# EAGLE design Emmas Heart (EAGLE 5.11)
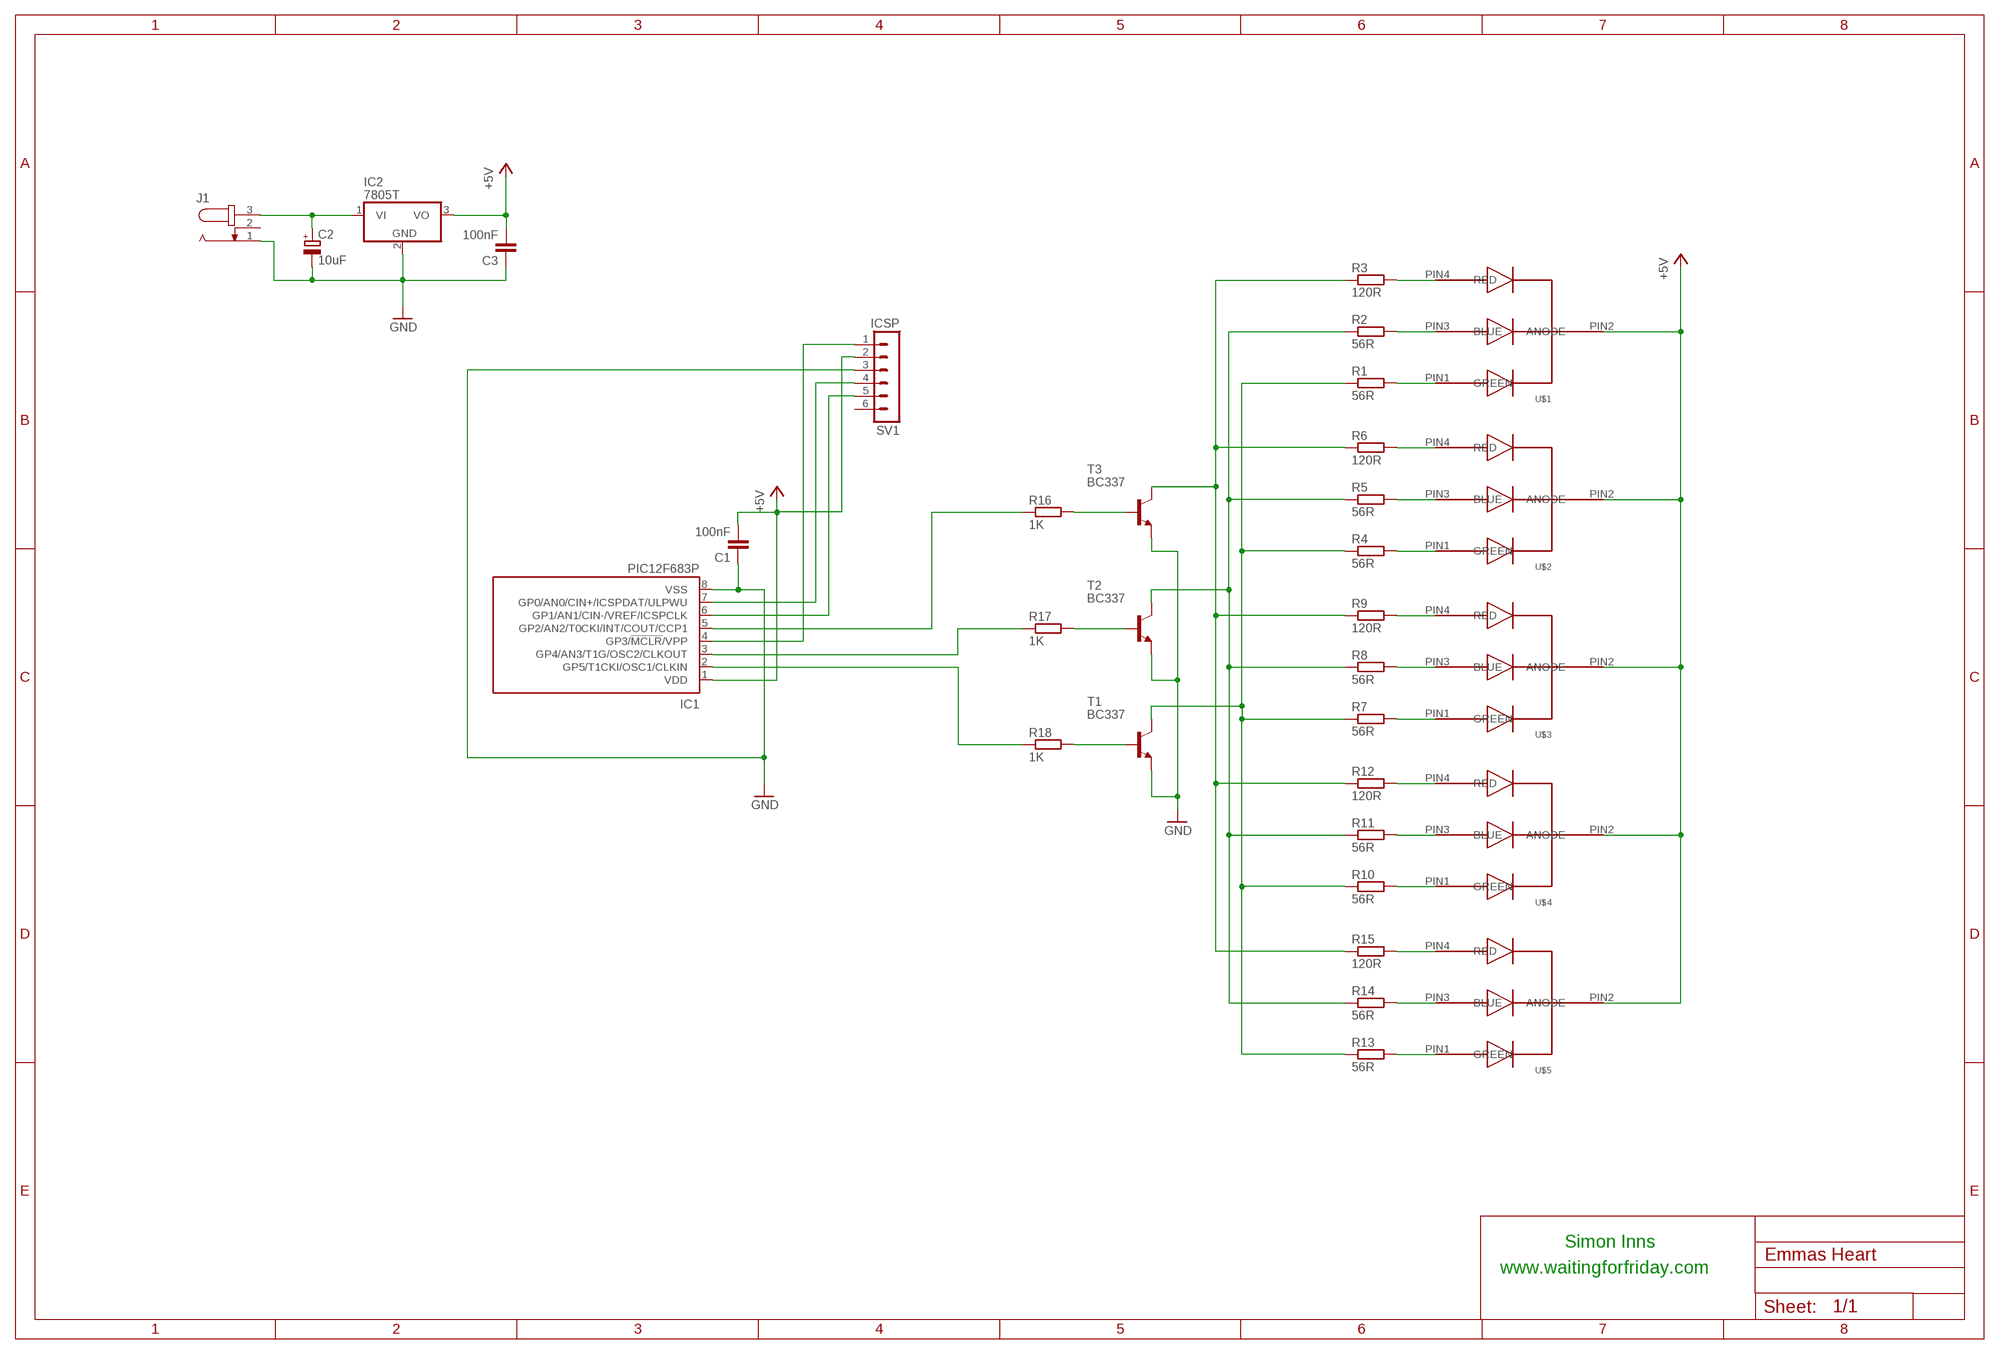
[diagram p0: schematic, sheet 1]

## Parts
C1  100nF  C-EU075-032X103  [C075-032X103]
C2  10uF  CPOL-EUE2.5-5  [E2,5-5]
C3  100nF  C-EU075-032X103  [C075-032X103]
IC1  PIC12F683P  [DIL8]
IC2  7805T  [TO220H]
J1  JACK-PLUG0  [SPC4077]
R1  56R  R-EU_0207/10  [0207/10]
R2  56R  R-EU_0207/10  [0207/10]
R3  120R  R-EU_0207/10  [0207/10]
R4  56R  R-EU_0207/10  [0207/10]
R5  56R  R-EU_0207/10  [0207/10]
R6  120R  R-EU_0207/10  [0207/10]
R7  56R  R-EU_0207/10  [0207/10]
R8  56R  R-EU_0207/10  [0207/10]
R9  120R  R-EU_0207/10  [0207/10]
R10  56R  R-EU_0207/10  [0207/10]
R11  56R  R-EU_0207/10  [0207/10]
R12  120R  R-EU_0207/10  [0207/10]
R13  56R  R-EU_0207/10  [0207/10]
R14  56R  R-EU_0207/10  [0207/10]
R15  120R  R-EU_0207/10  [0207/10]
R16  1K  R-EU_0207/10  [0207/10]
R17  1K  R-EU_0207/10  [0207/10]
R18  1K  R-EU_0207/10  [0207/10]
SV1  ICSP  MA06-1  [MA06-1]
T1  BC337  BC337-16-NPN-TO92-CBE  [TO92-CBE]
T2  BC337  BC337-16-NPN-TO92-CBE  [TO92-CBE]
T3  BC337  BC337-16-NPN-TO92-CBE  [TO92-CBE]
U$1  COMMON_ANODE_RGB_LED_KJ  [LED5MMRGB]
U$2  COMMON_ANODE_RGB_LED_KJ  [LED5MMRGB]
U$3  COMMON_ANODE_RGB_LED_KJ  [LED5MMRGB]
U$4  COMMON_ANODE_RGB_LED_KJ  [LED5MMRGB]
U$5  COMMON_ANODE_RGB_LED_KJ  [LED5MMRGB]

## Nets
+5V: C1.2 C3.2 IC1.1(VDD) IC2.3(VO) SV1.2 U$1.PIN2(ANODE) U$2.PIN2(ANODE) U$3.PIN2(ANODE) U$4.PIN2(ANODE) U$5.PIN2(ANODE)
GND: C1.1 C2.- C3.1 IC1.8(VSS) IC2.2(GND) J1.1 SV1.3 T1.E T2.E T3.E
N$1: C2.+ IC2.1(VI) J1.3
N$2: R3.1 R6.1 R9.1 R12.1 R15.1 T3.C
N$3: R2.1 R5.1 R8.1 R11.1 R14.1 T2.C
N$4: R1.1 R4.1 R7.1 R10.1 R13.1 T1.C
N$5: R3.2 U$1.PIN4(RED)
N$6: R2.2 U$1.PIN3(BLUE)
N$7: R1.2 U$1.PIN1(GREEN)
N$8: R6.2 U$2.PIN4(RED)
N$9: R5.2 U$2.PIN3(BLUE)
N$10: R4.2 U$2.PIN1(GREEN)
N$11: R9.2 U$3.PIN4(RED)
N$12: R8.2 U$3.PIN3(BLUE)
N$13: R7.2 U$3.PIN1(GREEN)
N$14: R12.2 U$4.PIN4(RED)
N$15: R11.2 U$4.PIN3(BLUE)
N$16: R10.2 U$4.PIN1(GREEN)
N$17: R15.2 U$5.PIN4(RED)
N$18: R14.2 U$5.PIN3(BLUE)
N$19: R13.2 U$5.PIN1(GREEN)
N$21: R16.2 T3.B
N$22: R17.2 T2.B
N$23: R18.2 T1.B
N$26: IC1.4(GP3/!MCLR!/VPP) SV1.1
N$27: IC1.7(GP0/AN0/CIN+/ICSPDAT/ULPWU) SV1.4
N$28: IC1.6(GP1/AN1/CIN-/VREF/ICSPCLK) SV1.5
N$29: IC1.5(GP2/AN2/T0CKI/INT/COUT/CCP1) R16.1
N$30: IC1.3(GP4/AN3/T1G/OSC2/CLKOUT) R17.1
N$31: IC1.2(GP5/T1CKI/OSC1/CLKIN) R18.1
Unconnected: J1.2 SV1.6

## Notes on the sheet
- Simon Inns
- www.waitingforfriday.com

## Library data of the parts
C1 C3 = rcl:C-EU: CAPACITOR, European symbol
C2 = rcl:CPOL-EU: POLARIZED CAPACITOR, European symbol
IC1 = microchip:PIC12F683: 8-Pin Flash-Based, 8-Bit CMOS Microcontrollers with nanoWatt Technology Source: http://ww1.microchip.com/downloads/en/DeviceDoc/41211D_.pdf; MF: MICROCHIP; MPN: PIC12F683-I/P; OC_FARNELL: 9759034; OC_NEWARK: 89H0442
IC2 = linear:78*: Positive VOLTAGE REGULATOR Source: http://cache.national.com/ds/LM/LM78L05.pdf http://www.fairchildsemi.com/ds/LM/LM7805.pdf
J1 = con-jack:JACK-PLUG: DC POWER JACK Power Jack, DC, Right Angle, Through Hole, Rated 5A at 16VDC, PC Terminals Distributor: Farnell (www.Farnell.de) Drawing: 84N1161.pdf / 84N1162.pdf Manufacturer: SPC Technology (www.spctechnology.com) Type: SPC4077 / SPC 4078; OC_FARNELL: unknown; OC_NEWARK: unknown
R1-R18 = rcl:R-EU_: RESISTOR, European symbol
SV1 = con-lstb:MA06-1: PIN HEADER; OC_FARNELL: unknown; OC_NEWARK: unknown
T1-T3 = transistor:*-NPN-: NPN Transistror BF959 corrected 2008.03.06
U$1-U$5 = simonslbr:COMMON_ANODE_RGB_LED_KJ: Common Anode RGB LED (5mm)

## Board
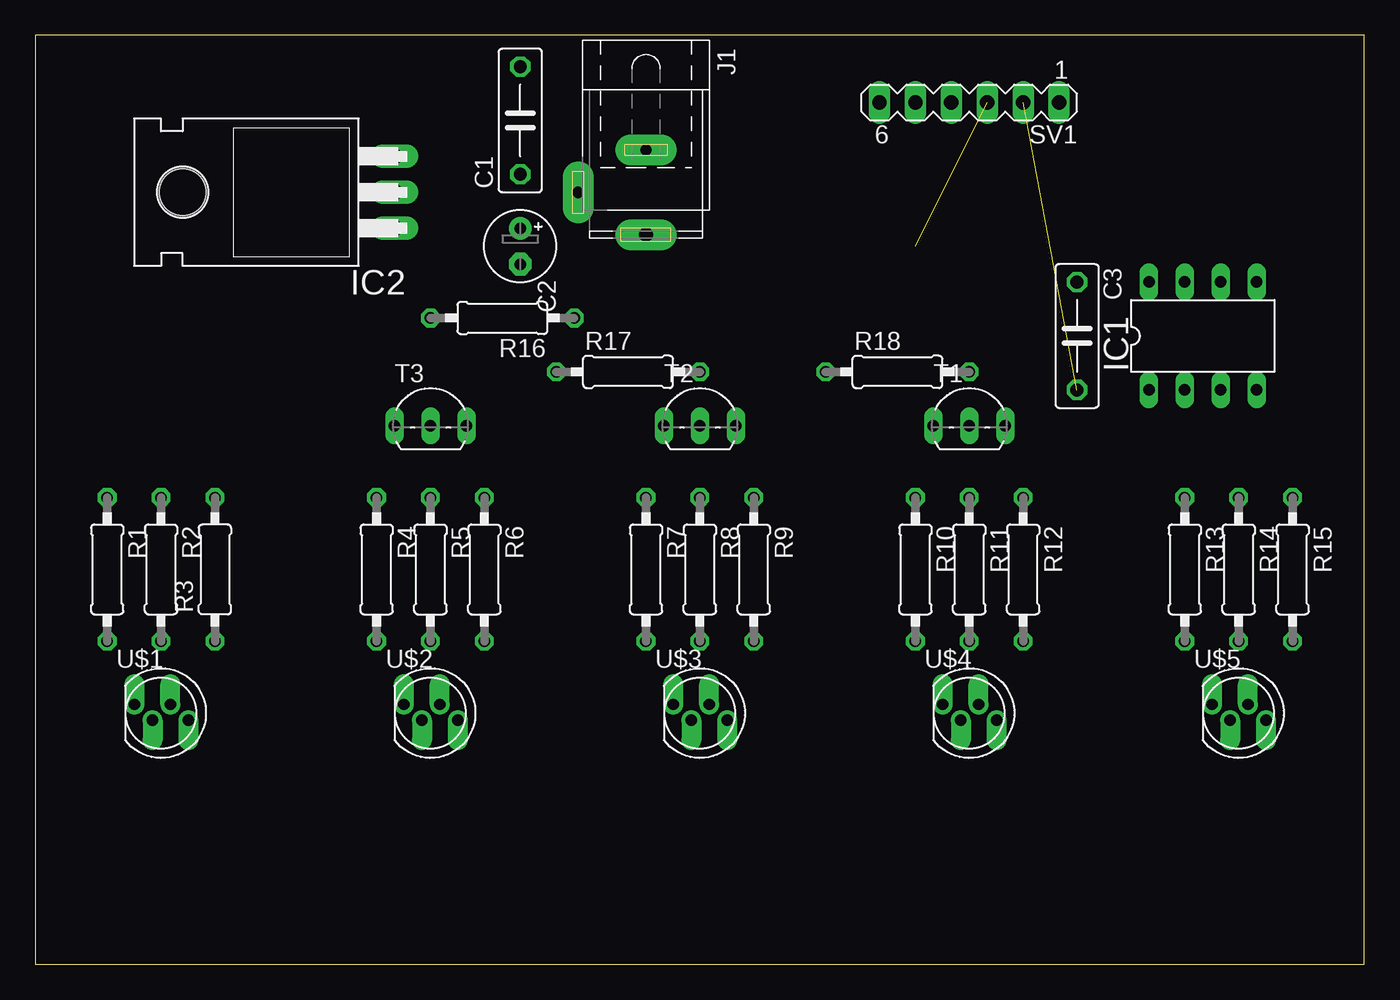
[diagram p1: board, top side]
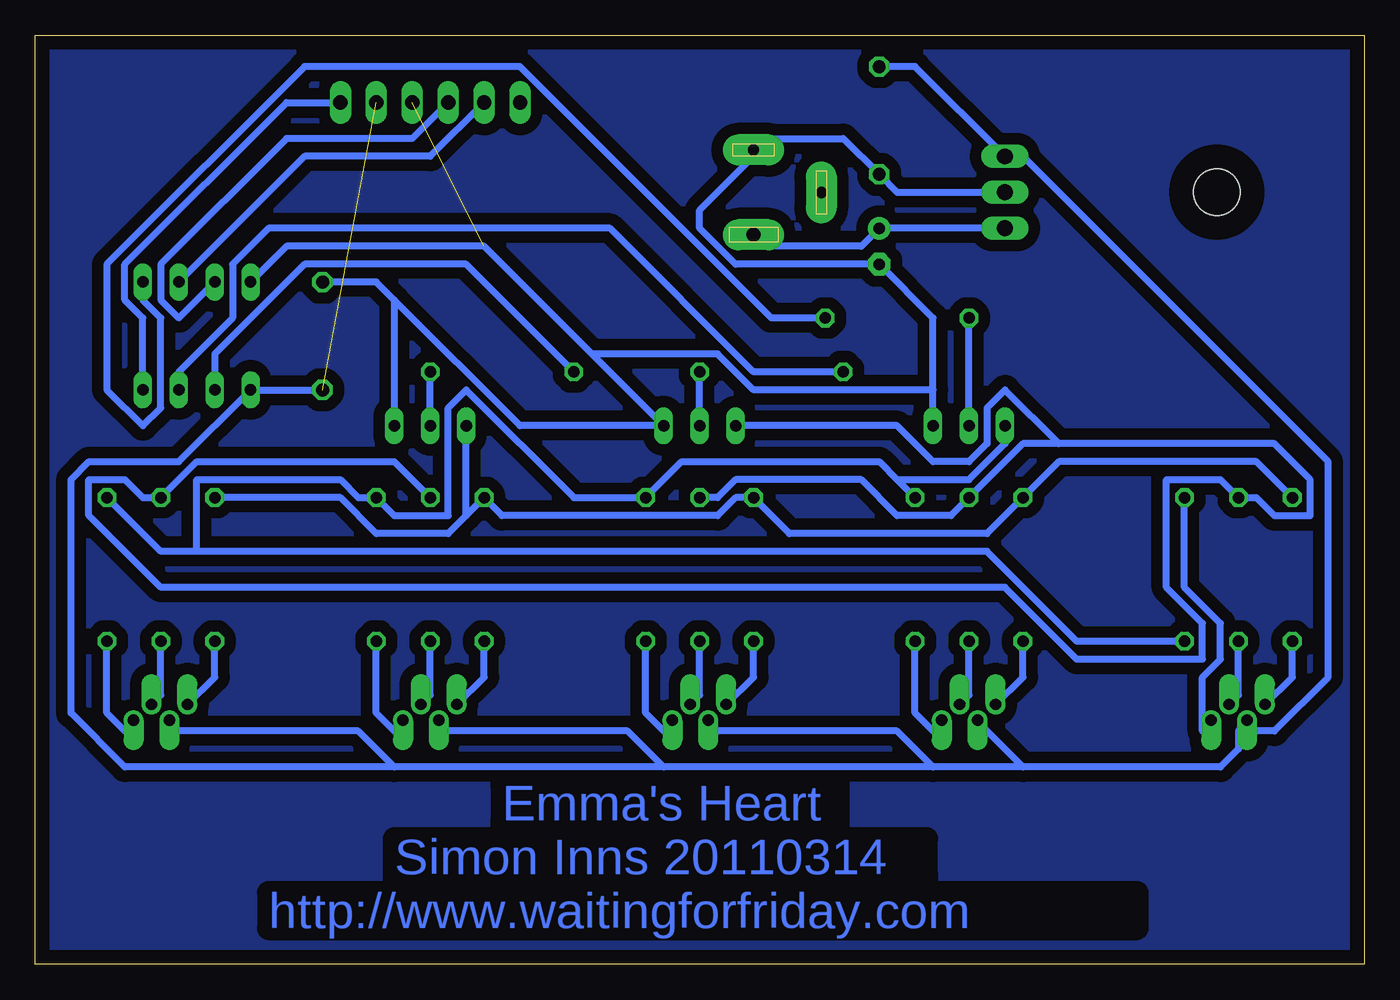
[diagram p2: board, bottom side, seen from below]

Size 93.96 x 65.71 mm. Coordinates in mm from the lower left corner, seen from the top.
Outline: 0,0 93.96,0 93.96,65.71 0,65.71 0,0
Copper layers (1*16): Top 0.035mm / dielectric 1.5mm / Bottom 0.035mm
Design rules "default *": minimum track width 20mil, minimum drill 24mil, track to track 8mil, track to pad 8mil, pad to pad 8mil, via to via 8mil, smd to smd 8mil, copper to edge 40mil, drill to drill 8mil, minimum pad ring 10mil, minimum via ring 8mil, stop-mask expansion 4mil, vias tented up to drill 0mil, thermal gap 10mil

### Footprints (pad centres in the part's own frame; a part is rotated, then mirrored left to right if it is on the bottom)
C075-032X103 = drill 0.914 octagon: 1 -3.81,0; 2 3.81,0
E2,5-5 = drill 0.813 pad 1.6 round: + -1.27,0 | drill 0.813 pad 1.6 octagon: - 1.27,0
DIL8 = drill 0.813 long: 1 -3.81,-3.81; 2 -1.27,-3.81; 3 1.27,-3.81; 4 3.81,-3.81; 5 3.81,3.81; 6 1.27,3.81; 7 -1.27,3.81; 8 -3.81,3.81
TO220H = drill 1.118 long: 1 -2.54,-10.16; 2 0,-10.16; 3 2.54,-10.16 | hole 3.302: 0,4.826
SPC4077 = drill 0.8 pad 2.184 long: 1 -3,0; 2 0,-4.8 | drill 1 pad 2.184 long: 3 3,0
0207/10 = drill 0.813 octagon: 1 -5.08,0; 2 5.08,0
MA06-1 = drill 1.016 long: 1 -6.35,0; 2 -3.81,0; 3 -1.27,0; 4 1.27,0; 5 3.81,0; 6 6.35,0
TO92-CBE = drill 0.813 long: B 0,0; C -2.54,0; E 2.54,0
LED5MMRGB = drill 0.8 pad 1.422 offset: PIN1 -1.88,0.61; PIN2 -0.61,-0.508; PIN3 0.66,0.61; PIN4 1.93,-0.508

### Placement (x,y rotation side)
C1  34.29,59.69 90 top
C2  34.29,50.8 270 top
C3  73.66,44.45 270 top
IC1  82.55,44.45 0 top
IC2  15.24,54.61 90 top
J1  43.18,54.61 270 top
R1  5.08,27.94 270 top
R2  8.89,27.94 270 top
R3  12.7,27.94 90 top
R4  24.13,27.94 270 top
R5  27.94,27.94 270 top
R6  31.75,27.94 270 top
R7  43.18,27.94 270 top
R8  46.99,27.94 270 top
R9  50.8,27.94 270 top
R10  62.23,27.94 270 top
R11  66.04,27.94 270 top
R12  69.85,27.94 270 top
R13  81.28,27.94 270 top
R14  85.09,27.94 270 top
R15  88.9,27.94 270 top
R16  33.02,45.72 180 top
R17  41.91,41.91 0 top
R18  60.96,41.91 0 top
SV1  66.04,60.96 180 top
T1  66.04,38.1 0 top
T2  46.99,38.1 0 top
T3  27.94,38.1 0 top
U$1  8.89,17.78 0 top
U$2  27.94,17.78 0 top
U$3  46.99,17.78 0 top
U$4  66.04,17.78 0 top
U$5  85.09,17.78 0 top

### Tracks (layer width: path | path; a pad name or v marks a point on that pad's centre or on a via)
+5V  (1 unrouted)
  Bottom 0.508: C1.2 31.75,63.5 IC2.3 24.13,57.15 2.54,35.56 2.54,20.32 6.35,16.51 7.62,16.51 U$1.PIN2 8.89,16.51 8.89,15.24 10.16,13.97 24.13,13.97 | C3.2 IC1.1 83.82,35.56 90.17,35.56 91.44,34.29 91.44,17.78 87.63,13.97 68.58,13.97 | 24.13,13.97 26.67,16.51 U$2.PIN2 | 30.48,13.97 33.02,16.51 45.72,16.51 U$3.PIN2 | 24.13,13.97 30.48,13.97 | 49.53,13.97 52.07,16.51 64.77,16.51 U$4.PIN2 | 30.48,13.97 49.53,13.97 | 68.58,13.97 71.12,16.51 83.82,16.51 U$5.PIN2 | 49.53,13.97 68.58,13.97
GND  (1 unrouted)
  Bottom 0.508: IC2.2 33.02,54.61 C1.1 36.83,58.42 43.18,58.42 J1.1 43.18,57.15 46.99,53.34 46.99,52.07 44.45,49.53 C2.- 30.48,45.72 30.48,40.64 | T3.E 30.48,40.64 | 68.58,46.99 69.85,48.26 C3.1 | 68.58,46.99 59.69,38.1 T2.E 54.61,43.18 | 68.58,46.99 T1.E | IC1.8 76.2,50.8 62.23,50.8 54.61,43.18 | 30.48,40.64 43.18,40.64 45.72,43.18 54.61,43.18
N$1
  Bottom 0.508: IC2.1 C2.+ 35.56,50.8 43.18,50.8 J1.3
N$2
  Bottom 0.508: 33.02,34.29 34.29,35.56 48.26,35.56 R9.1 55.88,33.02 63.5,40.64 64.77,39.37 64.77,31.75 68.58,31.75 R12.1 71.12,33.02 72.39,34.29 82.55,34.29 82.55,29.21 | 33.02,34.29 R6.1 | T3.C 25.4,36.83 27.94,34.29 33.02,34.29 | R3.1 20.32,22.86 26.67,29.21 82.55,29.21 | 82.55,29.21 85.09,29.21 R15.1
N$3
  Bottom 0.508: R11.1 68.58,35.56 82.55,35.56 R14.1 86.36,33.02 87.63,34.29 90.17,34.29 90.17,31.75 85.09,26.67 25.4,26.67 20.32,21.59 11.43,21.59 11.43,24.13 13.97,26.67 13.97,34.29 10.16,34.29 R2.1 7.62,33.02 6.35,31.75 3.81,31.75 3.81,34.29 6.35,36.83 21.59,36.83 | 21.59,36.83 24.13,36.83 R5.1 29.21,31.75 33.02,31.75 35.56,34.29 44.45,34.29 45.72,33.02 R8.1 | T2.C 33.02,38.1 30.48,35.56 27.94,35.56 26.67,36.83 26.67,39.37 25.4,40.64 21.59,36.83
N$4
  Bottom 0.508: R1.1 7.62,35.56 21.59,35.56 R4.1 26.67,30.48 40.64,30.48 R7.1 44.45,33.02 45.72,31.75 60.96,31.75 R10.1 63.5,31.75 | R13.1 72.39,33.02 69.85,30.48 64.77,30.48 63.5,31.75 | 63.5,31.75 T1.C
N$5
  Bottom 0.508: R3.2 12.7,26.67 10.16,24.13 10.16,21.59 11.43,20.32 11.43,16.51 U$1.PIN4
N$6
  Bottom 0.508: R2.2 8.89,19.05 U$1.PIN3
N$7
  Bottom 0.508: R1.2 5.08,20.32 U$1.PIN1
N$8
  Bottom 0.508: R6.2 31.75,17.78 30.48,16.51 U$2.PIN4
N$9
  Bottom 0.508: R5.2 27.94,19.05 U$2.PIN3
N$10
  Bottom 0.508: R4.2 24.13,20.32 U$2.PIN1
N$11
  Bottom 0.508: R9.2 50.8,17.78 49.53,16.51 U$3.PIN4
N$12
  Bottom 0.508: R8.2 46.99,19.05 U$3.PIN3
N$13
  Bottom 0.508: R7.2 43.18,20.32 U$3.PIN1
N$14
  Bottom 0.508: R12.2 69.85,17.78 68.58,16.51 U$4.PIN4
N$15
  Bottom 0.508: R11.2 66.04,19.05 U$4.PIN3
N$16
  Bottom 0.508: R10.2 62.23,20.32 U$4.PIN1
N$17
  Bottom 0.508: R15.2 88.9,17.78 87.63,16.51 U$5.PIN4
N$18
  Bottom 0.508: R14.2 85.09,19.05 U$5.PIN3
N$19
  Bottom 0.508: R13.2 81.28,20.32 U$5.PIN1
N$20
  pour Bottom (isolate 0.813): 0,66.04 93.98,66.04 93.98,0 0,0
N$21
  Bottom 0.508: T3.B R16.2
N$22
  Bottom 0.508: T2.B R17.2
N$23
  Bottom 0.508: T1.B R18.2
N$26
  Bottom 0.508: IC1.4 86.36,45.72 87.63,46.99 87.63,49.53 76.2,60.96 SV1.1
N$27
  Bottom 0.508: IC1.7 83.82,45.72 85.09,46.99 85.09,49.53 76.2,58.42 67.31,58.42 SV1.4
N$28
  Bottom 0.508: IC1.6 74.93,57.15 66.04,57.15 SV1.5
N$29
  Bottom 0.508: R16.1 41.91,45.72 59.69,63.5 74.93,63.5 88.9,49.53 88.9,40.64 86.36,38.1 85.09,39.37 85.09,45.72 86.36,46.99 IC1.5
N$30
  Bottom 0.508: R17.1 43.18,41.91 53.34,52.07 77.47,52.07 80.01,49.53 80.01,45.72 83.82,41.91 IC1.3
N$31
  Bottom 0.508: IC1.2 81.28,43.18 74.93,49.53 63.5,49.53 R18.1

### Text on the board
Bottom: Emma's Heart | Simon Inns 20110314 | http://www.waitingforfriday.com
